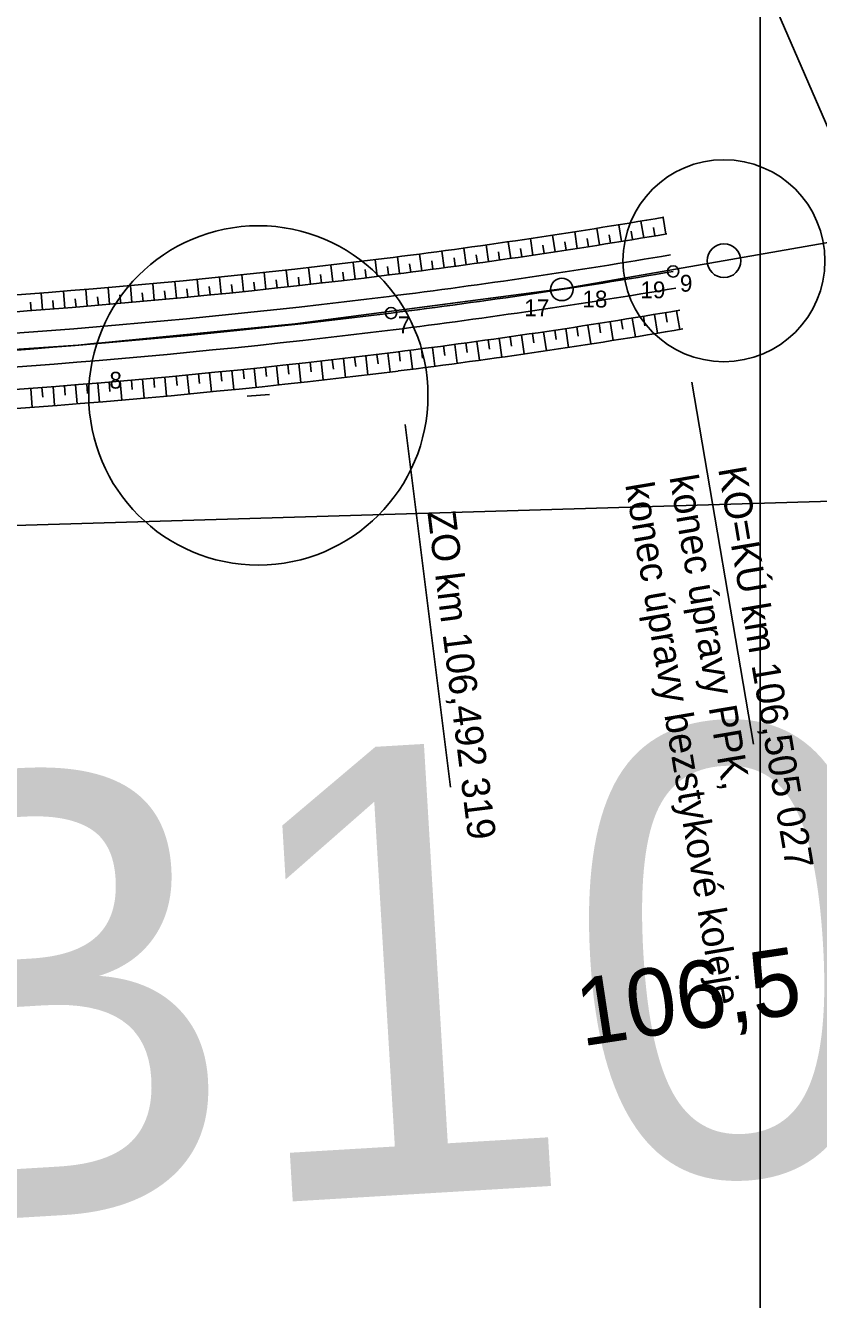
# Model space of a CAD drawing. Extents: x -759005 to -757278, y -1175311 to -1173953.
# Drawn here: x -758132.7 to -758097.4, y -1174804.5 to -1174747.7 of the extents above; entities that cross this region are included whole.
import ezdxf

# ---------------------------------------------------------------- set-up
doc = ezdxf.new("R2010")
doc.units = 0
for name, color, linetype in [('_NOR-návrh tenká', 7, 'Continuous'), ('_NOR-osa', 7, 'Continuous'), ('_NOR-popis', 7, 'Continuous'), ('_NOR-svahy', 7, 'Continuous'), ('_NOR-vytyčení', 7, 'Continuous'), ('G_Obvod stavby', 7, 'Continuous'), ('Vrstva 1', 7, 'Continuous'), ('Vrstva 52', 7, 'Continuous'), ('Vrstva 53', 7, 'Continuous'), ('Vrstva 62', 7, 'Continuous'), ('Vrstva 7', 7, 'Continuous')]:
    doc.layers.add(name, color=color, linetype=linetype)

# ---------------------------------------------------------------- blocks, each defined once
blk = doc.blocks.new('C513_1')
at = {"layer": 'Vrstva 7'}
blk.add_circle((0, 0), 0.75, dxfattribs=at)
blk = doc.blocks.new('POINT_DISPLAY')
blk.add_line((0, 0), (0, 0))

msp = doc.modelspace()

# ---------------------------------------------------------------- linework, layer by layer
at = {"layer": '_NOR-návrh tenká'}
for points in [[(-758133.729, -1174759.744), (-758132.727, -1174759.669), (-758131.726, -1174759.591), (-758130.725, -1174759.51), (-758129.724, -1174759.427), (-758128.724, -1174759.341), (-758127.724, -1174759.253), (-758126.724, -1174759.161), (-758125.725, -1174759.067), (-758124.727, -1174758.97), (-758123.728, -1174758.869), (-758122.731, -1174758.766), (-758121.733, -1174758.66), (-758120.736, -1174758.55), (-758119.74, -1174758.437), (-758118.744, -1174758.321), (-758117.749, -1174758.201), (-758116.752, -1174758.078)], [(-758133.674, -1174760.492), (-758132.67, -1174760.416), (-758131.667, -1174760.338), (-758130.664, -1174760.258), (-758129.661, -1174760.175), (-758128.659, -1174760.089), (-758127.657, -1174760), (-758126.655, -1174759.908), (-758125.654, -1174759.814), (-758124.653, -1174759.716), (-758123.652, -1174759.616), (-758122.652, -1174759.512), (-758121.652, -1174759.405), (-758120.653, -1174759.295), (-758119.654, -1174759.182), (-758118.656, -1174759.066), (-758117.658, -1174758.946), (-758116.659, -1174758.823)], [(-758133.604, -1174761.439), (-758132.598, -1174761.364), (-758131.592, -1174761.285), (-758130.586, -1174761.205), (-758129.581, -1174761.121), (-758128.576, -1174761.035), (-758127.571, -1174760.946), (-758126.567, -1174760.854), (-758125.563, -1174760.759), (-758124.559, -1174760.661), (-758123.556, -1174760.561), (-758122.553, -1174760.457), (-758121.55, -1174760.35), (-758120.548, -1174760.239), (-758119.546, -1174760.126), (-758118.544, -1174760.009), (-758117.543, -1174759.889), (-758116.542, -1174759.765)], [(-758133.493, -1174762.935), (-758132.483, -1174762.859), (-758131.474, -1174762.781), (-758130.464, -1174762.7), (-758129.455, -1174762.616), (-758128.446, -1174762.529), (-758127.437, -1174762.44), (-758126.428, -1174762.348), (-758125.42, -1174762.252), (-758124.411, -1174762.154), (-758123.404, -1174762.053), (-758122.396, -1174761.949), (-758121.388, -1174761.841), (-758120.381, -1174761.73), (-758119.375, -1174761.616), (-758118.368, -1174761.499), (-758117.362, -1174761.378), (-758116.357, -1174761.254)], [(-758133.42, -1174763.932), (-758132.407, -1174763.856), (-758131.395, -1174763.778), (-758130.383, -1174763.696), (-758129.371, -1174763.612), (-758128.359, -1174763.526), (-758127.347, -1174763.436), (-758126.336, -1174763.343), (-758125.324, -1174763.248), (-758124.313, -1174763.149), (-758123.302, -1174763.048), (-758122.291, -1174762.943), (-758121.281, -1174762.835), (-758120.27, -1174762.724), (-758119.26, -1174762.61), (-758118.251, -1174762.492), (-758117.241, -1174762.371), (-758116.233, -1174762.246)], [(-758133.357, -1174764.78), (-758132.343, -1174764.704), (-758131.328, -1174764.625), (-758130.314, -1174764.544), (-758129.299, -1174764.459), (-758128.285, -1174764.372), (-758127.271, -1174764.283), (-758126.257, -1174764.19), (-758125.243, -1174764.094), (-758124.229, -1174763.995), (-758123.216, -1174763.893), (-758122.202, -1174763.788), (-758121.189, -1174763.68), (-758120.176, -1174763.569), (-758119.163, -1174763.454), (-758118.151, -1174763.336), (-758117.138, -1174763.214), (-758116.129, -1174763.09)]]:
    msp.add_lwpolyline(points, dxfattribs=at)
for radius, start in [(288.55, 277.14072), (289.3, 277.14059), (290.25, 277.14043), (291.75, 277.14018), (292.75, 277.14001), (293.6, 277.13986)]:
    msp.add_arc((-758152.621, -1174471.766), radius, start, 279.64253, dxfattribs=at)
at = {"layer": '_NOR-osa'}
msp.add_lwpolyline([(-758133.549, -1174762.187), (-758132.541, -1174762.111), (-758131.533, -1174762.033), (-758130.525, -1174761.952), (-758129.518, -1174761.869), (-758128.511, -1174761.782), (-758127.504, -1174761.693), (-758126.498, -1174761.601), (-758125.491, -1174761.506), (-758124.485, -1174761.408), (-758123.48, -1174761.307), (-758122.474, -1174761.203), (-758121.469, -1174761.095), (-758120.465, -1174760.985), (-758119.46, -1174760.871), (-758118.456, -1174760.754), (-758117.453, -1174760.633), (-758116.45, -1174760.51)], dxfattribs=at)
for centre in [(-758103.878, -1174758.655), (-758116.45, -1174760.51)]:
    msp.add_circle(centre, 0.25, dxfattribs=at)
msp.add_arc((-758152.621, -1174471.766), 291, 277.1403, 279.64253, dxfattribs=at)
at = {"layer": '_NOR-popis'}
for p, q in [((-758103.04, -1174763.584), (-758100.3, -1174779.715)), ((-758115.828, -1174765.471), (-758113.804, -1174781.63))]:
    msp.add_line(p, q, dxfattribs=at)
msp.add_circle((-758108.841, -1174759.454), 0.5, dxfattribs=at)
at = {"layer": '_NOR-svahy'}
for points in [[(-758107.164, -1174757.473), (-758107.282, -1174756.732)], [(-758106.177, -1174757.314), (-758106.298, -1174756.574)], [(-758105.19, -1174757.152), (-758105.313, -1174756.412)], [(-758104.697, -1174757.069), (-758104.759, -1174756.7)], [(-758104.204, -1174756.986), (-758104.33, -1174756.247)], [(-758111.119, -1174758.074), (-758111.227, -1174757.332)], [(-758110.13, -1174757.929), (-758110.24, -1174757.187)], [(-758109.141, -1174757.78), (-758109.253, -1174757.039)], [(-758108.152, -1174757.628), (-758108.268, -1174756.887)], [(-758107.658, -1174757.551), (-758107.717, -1174757.181)], [(-758106.671, -1174757.394), (-758106.73, -1174757.024)], [(-758105.684, -1174757.233), (-758105.745, -1174756.863)], [(-758115.081, -1174758.62), (-758115.179, -1174757.877)], [(-758114.09, -1174758.489), (-758114.19, -1174757.746)], [(-758113.099, -1174758.354), (-758113.202, -1174757.611)], [(-758112.109, -1174758.216), (-758112.214, -1174757.473)], [(-758111.614, -1174758.145), (-758111.667, -1174757.774)], [(-758110.624, -1174758.002), (-758110.679, -1174757.631)], [(-758109.635, -1174757.855), (-758109.691, -1174757.484)], [(-758108.646, -1174757.705), (-758108.703, -1174757.334)], [(-758119.051, -1174759.112), (-758119.138, -1174758.367)], [(-758118.058, -1174758.994), (-758118.148, -1174758.249)], [(-758117.066, -1174758.873), (-758117.157, -1174758.128)], [(-758116.569, -1174758.811), (-758116.616, -1174758.439)], [(-758116.073, -1174758.749), (-758116.168, -1174758.005)], [(-758115.577, -1174758.685), (-758115.625, -1174758.313)], [(-758114.586, -1174758.555), (-758114.635, -1174758.183)], [(-758113.595, -1174758.422), (-758113.645, -1174758.05)], [(-758112.604, -1174758.285), (-758112.656, -1174757.914)], [(-758125.017, -1174759.752), (-758125.09, -1174759.005)], [(-758124.022, -1174759.653), (-758124.097, -1174758.906)], [(-758123.027, -1174759.551), (-758123.104, -1174758.805)], [(-758122.033, -1174759.446), (-758122.112, -1174758.7)], [(-758121.535, -1174759.392), (-758121.576, -1174759.02)], [(-758121.038, -1174759.338), (-758121.12, -1174758.592)], [(-758120.541, -1174759.283), (-758120.584, -1174758.91)], [(-758120.045, -1174759.226), (-758120.129, -1174758.481)], [(-758119.548, -1174759.17), (-758119.591, -1174758.797)], [(-758118.555, -1174759.054), (-758118.599, -1174758.681)], [(-758117.562, -1174758.934), (-758117.608, -1174758.562)], [(-758130.993, -1174760.284), (-758131.053, -1174759.537)], [(-758129.996, -1174760.202), (-758130.059, -1174759.455)], [(-758129, -1174760.118), (-758129.064, -1174759.371)], [(-758128.004, -1174760.031), (-758128.07, -1174759.284)], [(-758127.008, -1174759.94), (-758127.076, -1174759.194)], [(-758126.51, -1174759.894), (-758126.545, -1174759.521)], [(-758126.012, -1174759.847), (-758126.083, -1174759.101)], [(-758125.515, -1174759.8), (-758125.551, -1174759.427)], [(-758124.519, -1174759.703), (-758124.557, -1174759.33)], [(-758123.524, -1174759.602), (-758123.563, -1174759.229)], [(-758122.53, -1174759.499), (-758122.569, -1174759.126)], [(-758132.488, -1174760.402), (-758132.517, -1174760.028)], [(-758131.99, -1174760.364), (-758132.048, -1174759.616)], [(-758131.491, -1174760.324), (-758131.522, -1174759.951)], [(-758130.495, -1174760.244), (-758130.526, -1174759.87)], [(-758129.498, -1174760.161), (-758129.53, -1174759.787)], [(-758128.502, -1174760.075), (-758128.535, -1174759.701)], [(-758127.506, -1174759.986), (-758127.54, -1174759.613)], [(-758105.701, -1174760.732), (-758105.564, -1174761.571)], [(-758105.207, -1174760.651), (-758105.138, -1174761.071)], [(-758104.714, -1174760.57), (-758104.575, -1174761.408)], [(-758104.221, -1174760.488), (-758104.15, -1174760.907)], [(-758103.728, -1174760.405), (-758103.586, -1174761.243)], [(-758109.159, -1174761.272), (-758109.096, -1174761.692)], [(-758108.664, -1174761.197), (-758108.537, -1174762.038)], [(-758108.17, -1174761.122), (-758108.106, -1174761.542)], [(-758107.676, -1174761.046), (-758107.545, -1174761.886)], [(-758107.182, -1174760.968), (-758107.116, -1174761.388)], [(-758106.688, -1174760.89), (-758106.555, -1174761.73)], [(-758106.194, -1174760.812), (-758106.127, -1174761.231)], [(-758113.118, -1174761.839), (-758113.061, -1174762.26)], [(-758112.623, -1174761.771), (-758112.507, -1174762.613)], [(-758112.128, -1174761.702), (-758112.069, -1174762.123)], [(-758111.633, -1174761.633), (-758111.514, -1174762.474)], [(-758111.138, -1174761.562), (-758111.077, -1174761.983)], [(-758110.643, -1174761.491), (-758110.521, -1174762.332)], [(-758110.148, -1174761.419), (-758110.086, -1174761.839)], [(-758109.653, -1174761.346), (-758109.528, -1174762.187)], [(-758117.582, -1174762.411), (-758117.48, -1174763.255)], [(-758117.085, -1174762.351), (-758117.033, -1174762.773)], [(-758116.589, -1174762.29), (-758116.485, -1174763.134)], [(-758116.093, -1174762.229), (-758116.04, -1174762.65)], [(-758115.597, -1174762.166), (-758115.489, -1174763.009)], [(-758115.101, -1174762.102), (-758115.046, -1174762.524)], [(-758114.605, -1174762.038), (-758114.495, -1174762.88)], [(-758114.109, -1174761.972), (-758114.053, -1174762.393)], [(-758113.614, -1174761.906), (-758113.501, -1174762.748)], [(-758122.55, -1174762.97), (-758122.463, -1174763.815)], [(-758122.053, -1174762.918), (-758122.008, -1174763.34)], [(-758121.556, -1174762.865), (-758121.466, -1174763.71)], [(-758121.059, -1174762.811), (-758121.012, -1174763.233)], [(-758120.562, -1174762.756), (-758120.469, -1174763.601)], [(-758120.065, -1174762.701), (-758120.017, -1174763.123)], [(-758119.568, -1174762.644), (-758119.472, -1174763.489)], [(-758119.071, -1174762.588), (-758119.022, -1174763.01)], [(-758118.575, -1174762.53), (-758118.476, -1174763.374)], [(-758118.078, -1174762.471), (-758118.027, -1174762.893)], [(-758128.523, -1174763.54), (-758128.45, -1174764.387)], [(-758128.025, -1174763.496), (-758127.988, -1174763.919)], [(-758127.527, -1174763.452), (-758127.452, -1174764.299)], [(-758127.029, -1174763.407), (-758126.99, -1174763.83)], [(-758126.531, -1174763.361), (-758126.454, -1174764.208)], [(-758126.033, -1174763.315), (-758125.993, -1174763.738)], [(-758125.536, -1174763.268), (-758125.456, -1174764.114)], [(-758125.038, -1174763.22), (-758124.997, -1174763.643)], [(-758124.54, -1174763.171), (-758124.458, -1174764.017)], [(-758124.043, -1174763.122), (-758124, -1174763.545)], [(-758123.545, -1174763.072), (-758123.46, -1174763.918)], [(-758123.048, -1174763.021), (-758123.004, -1174763.444)], [(-758132.51, -1174763.864), (-758132.446, -1174764.712)], [(-758132.011, -1174763.826), (-758131.979, -1174764.249)], [(-758131.513, -1174763.787), (-758131.447, -1174764.634)], [(-758131.015, -1174763.747), (-758130.98, -1174764.171)], [(-758130.516, -1174763.707), (-758130.448, -1174764.554)], [(-758130.018, -1174763.666), (-758129.983, -1174764.09)], [(-758129.52, -1174763.625), (-758129.449, -1174764.472)], [(-758129.021, -1174763.582), (-758128.985, -1174764.006)]]:
    msp.add_lwpolyline(points, dxfattribs=at)
at = {"layer": 'G_Obvod stavby'}
msp.add_lwpolyline([(-758392.72, -1174840.756), (-758391.23, -1174838.56), (-758368.37, -1174821.64), (-758340.31, -1174807.33), (-758320.27, -1174796.89), (-758301, -1174790.21), (-758267.96, -1174782.93), (-758224.96, -1174775.27), (-758184.87, -1174772.83), (-758142.71, -1174770.26), (-758089.84, -1174768.68), (-758106.02, -1174731.44), (-758149.09, -1174725.67), (-758199.62, -1174726.6), (-758225.76, -1174732.36), (-758252.17, -1174738.18), (-758254.97, -1174739.34), (-758266.58, -1174744.16), (-758279.45, -1174749.49), (-758302.42, -1174759.02), (-758331.68, -1174770.24), (-758367.17, -1174799.81), (-758405.64, -1174832.2)], dxfattribs=at)
at = {"layer": 'Vrstva 1'}
for points in [[(-758275.047, -1174773.289), (-758265.484, -1174771.118), (-758253.61, -1174768.888), (-758243.69, -1174767.426), (-758231.371, -1174766.042), (-758219.363, -1174765.122), (-758206.915, -1174764.505), (-758194.225, -1174764.118), (-758182.013, -1174763.871), (-758170.862, -1174763.683), (-758162.019, -1174763.496), (-758153.195, -1174763.228), (-758152.069, -1174763.19), (-758141.836, -1174762.716), (-758130.402, -1174761.933), (-758120.726, -1174760.981), (-758108.612, -1174759.398), (-758096.467, -1174757.277), (-758085.591, -1174754.917)], [(-758115.85, -1174760.344), (-758108.612, -1174759.398), (-758106.047, -1174758.95)], [(-758196.804, -1174764.197), (-758194.225, -1174764.118), (-758182.013, -1174763.871), (-758170.862, -1174763.683), (-758162.019, -1174763.496), (-758153.195, -1174763.228), (-758152.069, -1174763.19), (-758141.836, -1174762.716), (-758130.402, -1174761.933), (-758129.559, -1174761.85)]]:
    msp.add_lwpolyline(points, dxfattribs=at)
at = {"layer": 'Vrstva 52'}
msp.add_line((-758122.865, -1174764.211), (-758121.867, -1174764.143), dxfattribs=at)
msp.add_circle((-758122.366, -1174764.177), 7.56, dxfattribs=at)
at = {"layer": 'Vrstva 62'}
for points in [[(-758100, -1174900), (-758100, -1174400), (-757400, -1174400), (-757400, -1174900), (-758100, -1174900)], [(-758600, -1174500), (-758100, -1174500), (-758100, -1175200), (-758600, -1175200), (-758600, -1174500)], [(-758600, -1174500), (-758100, -1174500), (-758100, -1175200), (-758600, -1175200), (-758600, -1174500)]]:
    msp.add_lwpolyline(points, dxfattribs=at)
at = {"layer": 'Vrstva 7'}
msp.add_circle((-758101.614, -1174758.176), 4.5, dxfattribs=at)

# ---------------------------------------------------------------- block references
at = {"layer": '_NOR-vytyčení'}
for p in [(-758105.639, -1174758.949), (-758103.878, -1174758.655), (-758108.225, -1174759.36), (-758110.814, -1174759.748), (-758116.45, -1174760.51), (-758129.305, -1174762.975)]:
    msp.add_blockref('POINT_DISPLAY', p, dxfattribs=at)
at = {"layer": 'Vrstva 7', "rotation": 9.906217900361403}
msp.add_blockref('C513_1', (-758101.614, -1174758.176), dxfattribs=at)

# ---------------------------------------------------------------- texts
at = {"layer": '_NOR-popis'}
for s, height, rotation, p in [('KO=KÚ km 106,505 027', 1.25, 279.6425, (-758101.878, -1174767.444)), ('konec úpravy bezstykové koleje', 1.25, 279.6425, (-758106.018, -1174768.148)), ('konec úpravy PPK,', 1.25, 279.6425, (-758104.046, -1174767.813)), ('ZO km 106,492 319', 1.25, 277.1403, (-758114.835, -1174769.378)), ('106,5', 3, 8.6527, (-758107.951, -1174793.189))]:
    msp.add_text(s, height=height, rotation=rotation, dxfattribs=at).set_placement(p)
at = {"layer": '_NOR-vytyčení'}
for s, p in [('9', (-758103.578, -1174759.555)), ('18', (-758107.925, -1174760.26)), ('19', (-758105.339, -1174759.849)), ('17', (-758110.514, -1174760.648)), ('7', (-758116.15, -1174761.41)), ('8', (-758129.005, -1174763.875))]:
    msp.add_text(s, height=0.75, rotation=360, dxfattribs=at).set_placement(p)
at = {"layer": 'Vrstva 53'}
msp.add_text('GB1017', height=20, rotation=3.4178, dxfattribs=at).set_placement((-758161.44, -1174802.517))

doc.saveas('drawing.dxf')
